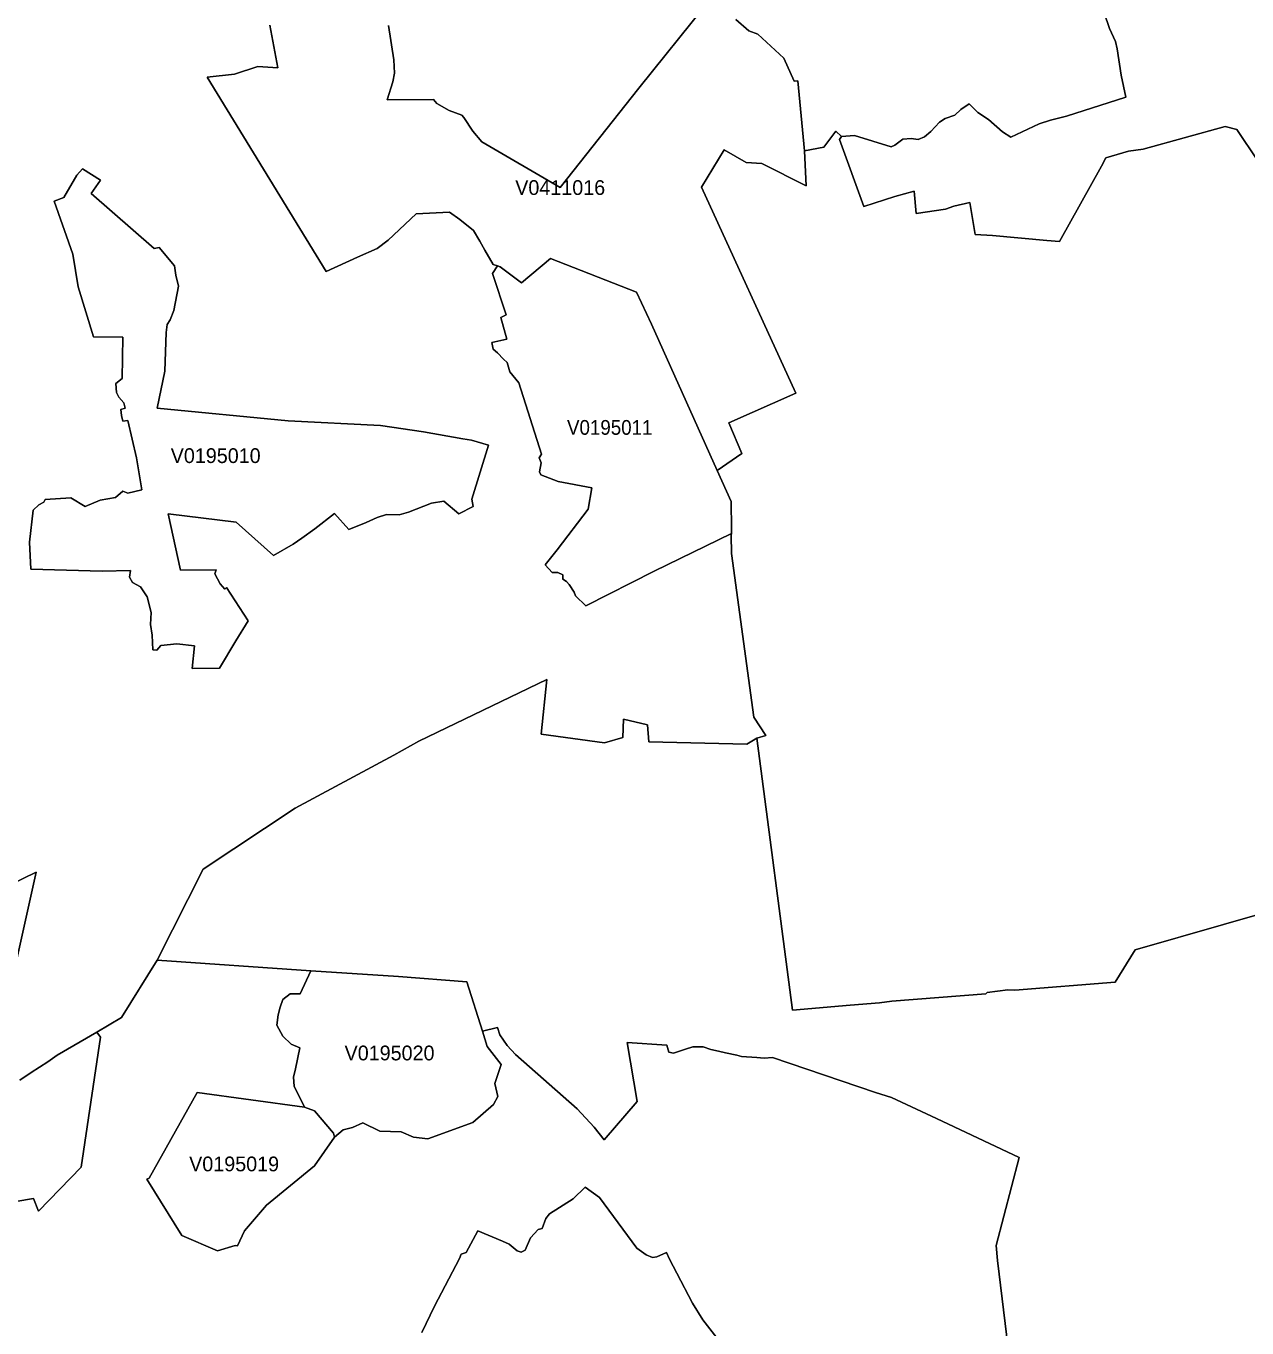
# Model space of a CAD drawing. Extents: x 369010 to 735936, y 6377141 to 6616555.
# Drawn here: x 479470 to 487749, y 6493257 to 6502081 of the extents above; entities that cross this region are included whole.
import ezdxf
from ezdxf.enums import TextEntityAlignment as Align

# ---------------------------------------------------------------- set-up
doc = ezdxf.new("R2010")
doc.units = 0
doc.header["$LTSCALE"] = 40
doc.layers.add('3', color=7, linetype='Continuous', lineweight=13)
doc.layers.add('4', color=7, linetype='Continuous')

msp = doc.modelspace()

# ---------------------------------------------------------------- linework, layer by layer
at = {"layer": '3'}
for points in [[(484078.68, 6502223.61), (483625.03, 6501660.07), (483091.62, 6500986.31), (482561.01, 6501295.3), (482499.44, 6501368.29), (482438.04, 6501460.47), (482423.97, 6501475.87), (482338.24, 6501509.13), (482255.49, 6501555.47), (482233.64, 6501583.77), (481918.85, 6501579.8), (481957.75, 6501702.28), (481968.01, 6501762.52), (481964.2, 6501852.06), (481926.96, 6502085.09)], [(481926.96, 6502085.09), (481964.2, 6501852.06), (481968.01, 6501762.52), (481957.75, 6501702.28), (481918.85, 6501579.8), (482233.64, 6501583.77), (482255.49, 6501555.47), (482338.24, 6501509.13), (482423.97, 6501475.87), (482438.04, 6501460.47), (482499.44, 6501368.29), (482561.01, 6501295.3), (483091.62, 6500986.31), (483625.03, 6501660.07), (484078.68, 6502223.61)], [(481123.44, 6502087.73), (481177.23, 6501796.78), (481042.34, 6501806.38), (480882.3, 6501753.75), (480696.77, 6501734.05), (481504.27, 6500418.13), (481717.77, 6500514.45), (481851.66, 6500572.38), (481924.32, 6500629.31), (482114.81, 6500807.56), (482340.89, 6500819.81), (482410.57, 6500770.82), (482503.08, 6500695.02), (482546.61, 6500623.02), (482580.87, 6500561.79), (482637.31, 6500465.46), (482667.1, 6500454.71), (482683.98, 6500448.75), (482829.46, 6500340.67), (483025.25, 6500505.35), (483610.14, 6500277.78), (483711.1, 6500060.14), (484156.47, 6499069.6), (484323.3, 6499183.97), (484234.92, 6499391.51), (484689.56, 6499592.6), (484049.55, 6500989.28), (484204.46, 6501241.51), (484351.6, 6501155.78), (484459.51, 6501150.15), (484760.23, 6500997.72), (484747.48, 6501234.73), (484703.79, 6501708.9), (484678.3, 6501706.41), (484607.8, 6501863.81), (484431.2, 6502025.17), (484370.46, 6502048.18), (484283.41, 6502126.3)], [(484283.41, 6502126.3), (484370.46, 6502048.18), (484431.2, 6502025.17), (484607.8, 6501863.81), (484678.3, 6501706.41), (484703.79, 6501708.9), (484747.48, 6501234.73), (484879.39, 6501258.89), (484961.31, 6501367.79), (484998.55, 6501333.2), (485086.77, 6501339.66), (485335.85, 6501261.21), (485361.5, 6501273.95), (485415.62, 6501313.84), (485470.4, 6501317.64), (485520.06, 6501311.19), (485560.93, 6501329.06), (485604.13, 6501366.8), (485662.72, 6501429.36), (485702.28, 6501454.85), (485768.64, 6501476.53), (485808.03, 6501514.76), (485865.46, 6501552.99), (485924.22, 6501495.73), (485995.55, 6501448.39), (486089.89, 6501362.99), (486147.65, 6501328.07), (486338.97, 6501417.44), (486415.43, 6501442.93), (486525.16, 6501469.74), (486926.34, 6501598.5), (486895.39, 6501747.13), (486867.26, 6501927.03), (486857.16, 6501976.68), (486816.45, 6502064.73), (486779.38, 6502169.33)], [(486779.38, 6502169.33), (486816.45, 6502064.73), (486857.16, 6501976.68), (486867.26, 6501927.03), (486895.39, 6501747.13), (486926.34, 6501598.5), (486525.16, 6501469.74), (486415.43, 6501442.93), (486338.97, 6501417.44), (486147.65, 6501328.07), (486089.89, 6501362.99), (485995.55, 6501448.39), (485924.22, 6501495.73), (485865.46, 6501552.99), (485808.03, 6501514.76), (485768.64, 6501476.53), (485702.28, 6501454.85), (485662.72, 6501429.36), (485604.13, 6501366.8), (485560.93, 6501329.06), (485520.06, 6501311.19), (485470.4, 6501317.64), (485415.62, 6501313.84), (485361.5, 6501273.95), (485335.85, 6501261.21), (485086.77, 6501339.66), (484998.55, 6501333.2), (484986.47, 6501311.19), (485150.65, 6500858.7), (485361.83, 6500925.23), (485492.09, 6500961.65), (485505.99, 6500811.04), (485704.92, 6500840.33), (485761.36, 6500859.69), (485869.77, 6500885.18), (485905.51, 6500667.05)], [(482966, 6499180.33), (482810.09, 6499662.94), (482750.01, 6499738.24), (482731.48, 6499801.13), (482707.15, 6499823.31), (482666.77, 6499865.68), (482637.31, 6499891.99), (482628.7, 6499935.85), (482730.49, 6499958.86), (482689.44, 6500104.83), (482724.69, 6500122.87), (482632.84, 6500402.9), (482667.1, 6500454.71), (482637.31, 6500465.46), (482580.87, 6500561.79), (482546.61, 6500623.02), (482503.08, 6500695.02), (482410.57, 6500770.82), (482340.89, 6500819.81), (482114.81, 6500807.56), (481924.32, 6500629.31), (481851.66, 6500572.38), (481717.77, 6500514.45), (481504.27, 6500418.13), (480696.77, 6501734.05), (480882.3, 6501753.75), (481042.34, 6501806.38), (481177.23, 6501796.78), (481123.44, 6502087.73)], [(487821.06, 6501168.03), (487680.88, 6501379.71), (487601.76, 6501400.23), (487044.18, 6501245.82), (486946.04, 6501233.07), (486790.46, 6501188.39), (486761.17, 6501132.28), (486477.33, 6500621.2), (486390.61, 6500626.33), (486024.01, 6500661.92), (485905.51, 6500667.05), (485869.77, 6500885.18), (485761.36, 6500859.69), (485704.92, 6500840.33), (485505.99, 6500811.04), (485492.09, 6500961.65), (485361.83, 6500925.23), (485150.65, 6500858.7), (484986.47, 6501311.19), (484998.55, 6501333.2)], [(485905.51, 6500667.05), (486024.01, 6500661.92), (486390.61, 6500626.33), (486477.33, 6500621.2), (486761.17, 6501132.28), (486790.46, 6501188.39), (486946.04, 6501233.07), (487044.18, 6501245.82), (487601.76, 6501400.23), (487680.88, 6501379.71), (487821.06, 6501168.03)], [(484998.55, 6501333.2), (484961.31, 6501367.79), (484879.39, 6501258.89), (484747.48, 6501234.73), (484760.23, 6500997.72), (484459.51, 6501150.15), (484351.6, 6501155.78), (484204.46, 6501241.51), (484049.55, 6500989.28), (484689.56, 6499592.6), (484234.92, 6499391.51), (484323.3, 6499183.97), (484156.47, 6499069.6), (484251.63, 6498858.25), (484253.29, 6498672.56), (484252.13, 6498640.95), (484251.8, 6498631.18), (484252.29, 6498507.22), (484405.22, 6497398.01), (484486.32, 6497273.22), (484424.92, 6497254.19), (484667.05, 6495412.13), (485056.81, 6495444.07), (485256.24, 6495460.62), (485341.31, 6495471.88), (485977.34, 6495522.85), (485987.44, 6495530.96), (486126.96, 6495549.66), (486174.29, 6495547.02), (486853.69, 6495601.14), (486989.57, 6495821.09), (488188.64, 6496163.68)], [(479428.18, 6494936.31), (479505.14, 6494988.94), (479616.53, 6495062.09), (479680.74, 6495106.28), (479950.02, 6495261.52), (480116.68, 6495362.31), (480358.98, 6495750.59), (480671.78, 6496367.92), (481294.74, 6496780.85), (481963.04, 6497140.32), (482134.17, 6497234.16), (483001.75, 6497653.05), (482963.68, 6497282.66), (483391.18, 6497222.41), (483515.97, 6497259.16), (483520.6, 6497382.29), (483684.12, 6497344.89), (483693.06, 6497228.87), (484357.06, 6497212.98), (484424.92, 6497254.19), (484486.32, 6497273.22), (484405.22, 6497398.01), (484252.29, 6498507.22), (484251.8, 6498631.18), (484252.13, 6498640.95), (483729.63, 6498386.07), (483264.4, 6498152.05), (483196.54, 6498219.91), (483186.95, 6498244.9), (483153.02, 6498295.71), (483134.48, 6498316.73), (483108.5, 6498332.28), (483108.5, 6498361.74), (483076.39, 6498377.8), (483037.33, 6498377.8), (482988.67, 6498430.26), (483070.1, 6498530.39), (483281.94, 6498807.44), (483305.94, 6498951.76), (483078.71, 6498993.14), (482961.2, 6499040.14), (482950.27, 6499060), (482961.53, 6499120.08), (482950.11, 6499154.18), (482966, 6499180.33)], [(488188.64, 6496163.68), (486989.57, 6495821.09), (486853.69, 6495601.14), (486174.29, 6495547.02), (486126.96, 6495549.66), (485987.44, 6495530.96), (485977.34, 6495522.85), (485341.31, 6495471.88), (485256.24, 6495460.62), (485056.81, 6495444.07), (484667.05, 6495412.13), (484424.92, 6497254.19), (484357.06, 6497212.98), (483693.06, 6497228.87), (483684.12, 6497344.89), (483520.6, 6497382.29), (483515.97, 6497259.16), (483391.18, 6497222.41), (482963.68, 6497282.66), (483001.75, 6497653.05), (482134.17, 6497234.16), (481963.04, 6497140.32), (481294.74, 6496780.85), (480671.78, 6496367.92), (480358.98, 6495750.59)], [(479001.68, 6496086.72), (479538.41, 6496346.4), (479402.37, 6495737.51)], [(480358.98, 6495750.59), (480116.68, 6495362.31), (479950.02, 6495261.52), (479974.35, 6495228.26), (479842.61, 6494348.11), (479554.3, 6494048.21), (479519.71, 6494134.77), (478720.82, 6493999.39), (478663.56, 6493955.2), (478604.64, 6493874.43), (478538.1, 6493746.33), (478516.59, 6493682.78), (478472.9, 6493625.02), (478412.98, 6493593.74), (478386.17, 6493567.92), (478352.41, 6493502.05), (478336.35, 6493451.57), (478297.46, 6493440.15), (478296.3, 6493390.33), (478177.64, 6493325.62), (478062.28, 6493282.92), (477977.38, 6493261.24), (477808.73, 6493195.87)], [(480358.98, 6495750.59), (481399.83, 6495676.94), (481994.49, 6495639.37), (482458.89, 6495603.78), (482564.48, 6495269.14), (482665.77, 6495293.13), (482682.82, 6495245.14), (482731.48, 6495170.66), (482789.57, 6495109.75), (483205.98, 6494743.33), (483321.5, 6494617.71), (483388.86, 6494533.14), (483612.95, 6494792.81), (483546.42, 6495192.34), (483815.7, 6495173.47), (483827.45, 6495126.8), (483860.71, 6495120.35), (483941.81, 6495146.99), (483989.97, 6495161.72), (484060.97, 6495162.38), (484114.1, 6495144.35), (484165.9, 6495133.42), (484211.75, 6495121.51), (484289.2, 6495106.78), (484322.14, 6495096.35), (484423.92, 6495089.89), (484474.57, 6495085.43), (484532.16, 6495091.05), (485229.76, 6494853.72), (485338, 6494820.45), (485643.19, 6494675.97), (486204.91, 6494411.99), (486048.01, 6493816.01), (486057.78, 6493714.22), (486149.96, 6492953.57)], [(481261.31, 6495521.36), (481328.5, 6495521.36), (481399.83, 6495676.94), (480358.98, 6495750.59)], [(486149.96, 6492953.57), (486057.78, 6493714.22), (486048.01, 6493816.01), (486204.91, 6494411.99), (485643.19, 6494675.97), (485338, 6494820.45), (485229.76, 6494853.72), (484532.16, 6495091.05), (484474.57, 6495085.43), (484423.92, 6495089.89), (484322.14, 6495096.35), (484289.2, 6495106.78), (484211.75, 6495121.51), (484165.9, 6495133.42), (484114.1, 6495144.35), (484060.97, 6495162.38), (483989.97, 6495161.72), (483941.81, 6495146.99), (483860.71, 6495120.35), (483827.45, 6495126.8), (483815.7, 6495173.47), (483546.42, 6495192.34), (483612.95, 6494792.81), (483388.86, 6494533.14), (483321.5, 6494617.71), (483205.98, 6494743.33), (482789.57, 6495109.75), (482731.48, 6495170.66), (482682.82, 6495245.14), (482665.77, 6495293.13), (482564.48, 6495269.14), (482597.42, 6495164.7), (482690.43, 6495042.73), (482647.73, 6494913.14), (482668.92, 6494827.07), (482638.3, 6494772.62), (482499.94, 6494649.49), (482193.59, 6494539.59), (482096.27, 6494550.68), (482012.2, 6494586.27), (481867.88, 6494590.9), (481752.36, 6494647.83), (481683.18, 6494615.06), (481618.96, 6494600), (481561.2, 6494550.52), (481424.66, 6494356.38), (481101.26, 6494088.76), (480951.81, 6493916.47), (480903.32, 6493813.53), (480888.09, 6493816.84), (480768.77, 6493780.59), (480526.14, 6493885.03), (480288.14, 6494266.02), (480304.69, 6494271.81), (480630.57, 6494854.22), (481358.29, 6494753.42), (481288.78, 6494896.25), (481283.65, 6494957.66), (481296.23, 6495014.09), (481325.19, 6495155.93), (481268.09, 6495181.91), (481210.33, 6495233.88), (481169.78, 6495310.18), (481180.04, 6495379.36), (481193.78, 6495432.49), (481211.66, 6495483.79), (481261.31, 6495521.36)], [(478720.82, 6493999.39), (479519.71, 6494134.77), (479554.3, 6494048.21), (479842.61, 6494348.11), (479974.35, 6495228.26), (479950.02, 6495261.52), (479680.74, 6495106.28), (479616.53, 6495062.09), (479505.14, 6494988.94), (479428.18, 6494936.31)], [(482153.37, 6493226.48), (482239.6, 6493404.24), (482409.74, 6493728.95), (482420.99, 6493757.92), (482454.26, 6493768.18), (482533.2, 6493914.98), (482700.2, 6493846.63), (482745.38, 6493826.27), (482800.49, 6493780.76), (482827.31, 6493771.16), (482853.62, 6493784.07), (482889.53, 6493867.32), (482943.32, 6493925.08), (482969.64, 6493932.36), (482993.97, 6493999.39), (483018.96, 6494030.83), (483179.17, 6494132.45), (483261.75, 6494211.9), (483359.07, 6494141.23), (483612.13, 6493798.63), (483673.86, 6493752.62), (483717.39, 6493735.91), (483746.68, 6493740.37), (483812.05, 6493769.83), (483833.74, 6493723), (483881.9, 6493628.82), (483989.81, 6493425.59), (484059.65, 6493312.38), (484225.15, 6493098.55)], [(484225.15, 6493098.55), (484059.65, 6493312.38), (483989.81, 6493425.59), (483881.9, 6493628.82), (483833.74, 6493723), (483812.05, 6493769.83), (483746.68, 6493740.37), (483717.39, 6493735.91), (483673.86, 6493752.62), (483612.13, 6493798.63), (483359.07, 6494141.23), (483261.75, 6494211.9), (483179.17, 6494132.45), (483018.96, 6494030.83), (482993.97, 6493999.39), (482969.64, 6493932.36), (482943.32, 6493925.08), (482889.53, 6493867.32), (482853.62, 6493784.07), (482827.31, 6493771.16), (482800.49, 6493780.76), (482745.38, 6493826.27), (482700.2, 6493846.63), (482533.2, 6493914.98), (482454.26, 6493768.18), (482420.99, 6493757.92), (482409.74, 6493728.95), (482239.6, 6493404.24), (482153.37, 6493226.48)]]:
    msp.add_lwpolyline(points, dxfattribs=at)
for points in [[(479853.53, 6501113.91), (479974.84, 6501035.29), (479910.96, 6500944.93), (480338.95, 6500572.55), (480372.22, 6500580.82), (480475.99, 6500455.86), (480484.93, 6500392.97), (480502.97, 6500318.99), (480471.85, 6500152.33), (480446.86, 6500090.76), (480426.17, 6500058.49), (480419.72, 6500004.54), (480410.62, 6499742.21), (480359.81, 6499491.14), (481247.57, 6499404.75), (481872.18, 6499372.64), (482163.63, 6499331.6), (482430.59, 6499284.26), (482490.34, 6499275.16), (482605.53, 6499240.57), (482492.66, 6498874.81), (482501.59, 6498825.65), (482403.62, 6498775.5), (482303.15, 6498861.56), (482218.58, 6498847.99), (482063.17, 6498785.27), (482000.45, 6498769.21), (481913.72, 6498770.37), (481850.83, 6498749.85), (481775.53, 6498715.42), (481659.01, 6498669.75), (481562.03, 6498778.32), (481426.81, 6498673.06), (481339.09, 6498610.33), (481280.34, 6498570.28), (481147.11, 6498493.32), (480895.54, 6498719.07), (480432.63, 6498775.34), (480516.54, 6498394.02), (480758.01, 6498395.84), (480750.4, 6498369.02), (480786.48, 6498299.84), (480817.26, 6498264.43), (480830, 6498275.35), (480974.82, 6498050.76), (480892.4, 6497915.38), (480781.01, 6497728.03), (480596.31, 6497727.03), (480613.03, 6497879.96), (480492.37, 6497894.52), (480383.14, 6497882.61), (480356.17, 6497851.82), (480330.02, 6497853.15), (480325.55, 6497953.78), (480312.97, 6498024.94), (480318.76, 6498106.87), (480290.29, 6498213.45), (480246.77, 6498279.16), (480191.16, 6498309.94), (480171.13, 6498344.7), (480178.91, 6498390.21), (479986.43, 6498386.9), (479502.83, 6498400.8), (479493.23, 6498583.35), (479517.39, 6498799.83), (479557.11, 6498836.24), (479591.04, 6498854.78), (479599.32, 6498871.5), (479772.43, 6498884.07), (479869.75, 6498824.49), (479972.69, 6498867.52), (480075.97, 6498885.56), (480127.11, 6498928.76), (480160.37, 6498915.85), (480254.88, 6498937.7), (480217.97, 6499155), (480158.88, 6499408.56), (480126.78, 6499403.26), (480116.02, 6499440.99), (480112.05, 6499481.38), (480141.51, 6499491.14), (480133.73, 6499527.06), (480097.98, 6499566.28), (480083.41, 6499598.39), (480079.11, 6499658.14), (480121.31, 6499692.73), (480125.45, 6499973.26), (479926.35, 6499974.41), (479822.41, 6500312.37), (479787.66, 6500535.8), (479660.88, 6500894.78), (479726.75, 6500917.79), (479814.97, 6501070.71)], [(479853.53, 6501113.91), (479814.97, 6501070.71), (479726.75, 6500917.79), (479660.88, 6500894.78), (479787.66, 6500535.8), (479822.41, 6500312.37), (479926.35, 6499974.41), (480125.45, 6499973.26), (480121.31, 6499692.73), (480079.11, 6499658.14), (480083.41, 6499598.39), (480097.98, 6499566.28), (480133.73, 6499527.06), (480141.51, 6499491.14), (480112.05, 6499481.38), (480116.02, 6499440.99), (480126.78, 6499403.26), (480158.88, 6499408.56), (480217.97, 6499155), (480254.88, 6498937.7), (480160.37, 6498915.85), (480127.11, 6498928.76), (480075.97, 6498885.56), (479972.69, 6498867.52), (479869.75, 6498824.49), (479772.43, 6498884.07), (479599.32, 6498871.5), (479591.04, 6498854.78), (479557.11, 6498836.24), (479517.39, 6498799.83), (479493.23, 6498583.35), (479502.83, 6498400.8), (479986.43, 6498386.9), (480178.91, 6498390.21), (480171.13, 6498344.7), (480191.16, 6498309.94), (480246.77, 6498279.16), (480290.29, 6498213.45), (480318.76, 6498106.87), (480312.97, 6498024.94), (480325.55, 6497953.78), (480330.02, 6497853.15), (480356.17, 6497851.82), (480383.14, 6497882.61), (480492.37, 6497894.52), (480613.03, 6497879.96), (480596.31, 6497727.03), (480781.01, 6497728.03), (480892.4, 6497915.38), (480974.82, 6498050.76), (480830, 6498275.35), (480817.26, 6498264.43), (480786.48, 6498299.84), (480750.4, 6498369.02), (480758.01, 6498395.84), (480516.54, 6498394.02), (480432.63, 6498775.34), (480895.54, 6498719.07), (481147.11, 6498493.32), (481280.34, 6498570.28), (481339.09, 6498610.33), (481426.81, 6498673.06), (481562.03, 6498778.32), (481659.01, 6498669.75), (481775.53, 6498715.42), (481850.83, 6498749.85), (481913.72, 6498770.37), (482000.45, 6498769.21), (482063.17, 6498785.27), (482218.58, 6498847.99), (482303.15, 6498861.56), (482403.62, 6498775.5), (482501.59, 6498825.65), (482492.66, 6498874.81), (482605.53, 6499240.57), (482490.34, 6499275.16), (482430.59, 6499284.26), (482163.63, 6499331.6), (481872.18, 6499372.64), (481247.57, 6499404.75), (480359.81, 6499491.14), (480410.62, 6499742.21), (480419.72, 6500004.54), (480426.17, 6500058.49), (480446.86, 6500090.76), (480471.85, 6500152.33), (480502.97, 6500318.99), (480484.93, 6500392.97), (480475.99, 6500455.86), (480372.22, 6500580.82), (480338.95, 6500572.55), (479910.96, 6500944.93), (479974.84, 6501035.29)], [(482667.1, 6500454.71), (482632.84, 6500402.9), (482724.69, 6500122.87), (482689.44, 6500104.83), (482730.49, 6499958.86), (482628.7, 6499935.85), (482637.31, 6499891.99), (482666.77, 6499865.68), (482707.15, 6499823.31), (482731.48, 6499801.13), (482750.01, 6499738.24), (482810.09, 6499662.94), (482966, 6499180.33), (482950.11, 6499154.18), (482961.53, 6499120.08), (482950.27, 6499060), (482961.2, 6499040.14), (483078.71, 6498993.14), (483305.94, 6498951.76), (483281.94, 6498807.44), (483070.1, 6498530.39), (482988.67, 6498430.26), (483037.33, 6498377.8), (483076.39, 6498377.8), (483108.5, 6498361.74), (483108.5, 6498332.28), (483134.48, 6498316.73), (483153.02, 6498295.71), (483186.95, 6498244.9), (483196.54, 6498219.91), (483264.4, 6498152.05), (483729.63, 6498386.07), (484252.13, 6498640.95), (484253.29, 6498672.56), (484251.63, 6498858.25), (484156.47, 6499069.6), (483711.1, 6500060.14), (483610.14, 6500277.78), (483025.25, 6500505.35), (482829.46, 6500340.67), (482683.98, 6500448.75)], [(479001.68, 6496086.72), (479005.49, 6496052.8), (478721.81, 6495102.31), (478964.77, 6494982.65), (479075.5, 6495152.95), (479227.1, 6495449.7), (479318.62, 6495631.09), (479402.37, 6495737.51), (479538.41, 6496346.4)], [(481399.83, 6495676.94), (481328.5, 6495521.36), (481261.31, 6495521.36), (481211.66, 6495483.79), (481193.78, 6495432.49), (481180.04, 6495379.36), (481169.78, 6495310.18), (481210.33, 6495233.88), (481268.09, 6495181.91), (481325.19, 6495155.93), (481296.23, 6495014.09), (481283.65, 6494957.66), (481288.78, 6494896.25), (481358.29, 6494753.42), (481425.65, 6494729.1), (481553.59, 6494577.33), (481561.2, 6494550.52), (481618.96, 6494600), (481683.18, 6494615.06), (481752.36, 6494647.83), (481867.88, 6494590.9), (482012.2, 6494586.27), (482096.27, 6494550.68), (482193.59, 6494539.59), (482499.94, 6494649.49), (482638.3, 6494772.62), (482668.92, 6494827.07), (482647.73, 6494913.14), (482690.43, 6495042.73), (482597.42, 6495164.7), (482564.48, 6495269.14), (482458.89, 6495603.78), (481994.49, 6495639.37)], [(481561.2, 6494550.52), (481553.59, 6494577.33), (481425.65, 6494729.1), (481358.29, 6494753.42), (480630.57, 6494854.22), (480304.69, 6494271.81), (480288.14, 6494266.02), (480526.14, 6493885.03), (480768.77, 6493780.59), (480888.09, 6493816.84), (480903.32, 6493813.53), (480951.81, 6493916.47), (481101.26, 6494088.76), (481424.66, 6494356.38)]]:
    msp.add_lwpolyline(points, close=True, dxfattribs=at)

# ---------------------------------------------------------------- texts
at = {"layer": '4'}
for s, p in [('V0411016', (483091.61, 6500936.3)), ('V0195010', (480755.56, 6499119.36)), ('V0195020', (481934.46, 6495071.05)), ('V0195019', (480880.59, 6494319.09))]:
    msp.add_text(s, height=100, dxfattribs=at).set_placement(p, align=Align.CENTER)
at = {"layer": '4', "width": 0.95}
msp.add_text('V0195011', height=100, dxfattribs=at).set_placement((483427.53, 6499310.62), align=Align.CENTER)

doc.saveas('drawing.dxf')
